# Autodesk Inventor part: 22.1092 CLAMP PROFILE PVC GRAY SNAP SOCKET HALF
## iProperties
Created: 2007-04
Part Number: 22.1092 CLAMP PROFILE PVC GRAY SNAP SOCKET HALF
Document SubType Name: Modeling
Designer: Andy Moles
Material: PVC-U
Density: 1.4 g/cm^3
Author: Andy Moles
